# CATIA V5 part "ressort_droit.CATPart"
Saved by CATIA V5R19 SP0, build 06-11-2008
Part number: ressort_droit
Bounding box of the stored display mesh (mm): x 0 to 15, y -117.604 to -3.604, z -8.645 to 31.355
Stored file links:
  H:\EU_thinkMotion\IAO_2010\iao\IAO_MMS_Groupe3\PB\jpeguet\jpeguet_IAO\jpeguet_IAO\ressort_droit.CATPart
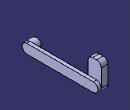
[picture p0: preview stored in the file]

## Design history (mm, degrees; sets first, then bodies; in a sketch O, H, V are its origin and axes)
Parameters
  tige = 100 mm
Body1 (main body)
  Sketch1 on yz-plane, origin (0, 0, 0), H (0, 1, 0), V (0, 0, 1)
    line L1 (-23.6044, 31.3549) -> (-3.6044, 31.3549)
    line L2 (-3.6044, 31.3549) -> (-3.6044, -8.6451)
    line L3 (-3.6044, -8.6451) -> (-23.6044, -8.6451)
    line L4 (-23.6044, -8.6451) -> (-23.6044, 31.3549)
    length L1 = 20
    length L2 = 40
    horizontal: L1 H, L3 H
    vertical: L2 V, L4 V
  Pad1: profile Sketch1, direction (1, 0, 0), length 10
  Sketch2 on start face of Pad1, origin (0, 0, 0), H (0, -1, 0), V (0, 0, 1)
    arc A1 centre (13.6044, 21.3549) radius 7 from (14.6044, 14.4267) to (12.6044, 14.4267) ccw
    point P1 (13.6044, 21.3549)
    point P2 (12.6044, 12.5144)
    line L1 (14.6044, 14.4267) -> (14.6044, 17.3549)
    line L2 (14.6044, 17.3549) -> (12.6044, 17.3549)
    line L3 (12.6044, 17.3549) -> (12.6044, 14.4267)
    point P3 (14.6044, 12.5144)
    reference projected line E1 (23.6044, 31.3549) -> (23.6044, -28.6451) from edge [start face of Pad1 | face of Pad1 from Sketch1.L4]
    reference projected line E2 (3.6044, 31.3549) -> (23.6044, 31.3549) from edge [start face of Pad1 | face of Pad1 from Sketch1.L1]
    reference projected line E3 (23.6044, 31.3549) -> (23.6044, -28.6451) from edge [start face of Pad1 | face of Pad1 from Sketch1.L4]
    reference projected line E4 (3.6044, 31.3549) -> (23.6044, 31.3549) from edge [start face of Pad1 | face of Pad1 from Sketch1.L1]
    distance P1 E1 = 10
    distance E2 P1 = 10
    distance L1 E3 = 9
    radius A1 = 7
    distance L2 E4 = 14
    horizontal: L2 H
    vertical: L1 V, L3 V
  Pocket1: profile Sketch2, direction (1, 0, 0), length 3
  Sketch3 on end face of Pad1, origin (10, 0, 0), H (0, 1, 0), V (0, 0, 1)
    construction line L1 (-10.6044, -1.6451) -> (-110.6044, -1.6451)
    point P1 (-10.6044, -1.6451)
    line L2 (-10.6044, -8.6451) -> (-110.6044, -8.6451)
    line L3 (-110.6044, 5.3549) -> (-10.6044, 5.3549)
    arc A1 centre (-110.6044, -1.6451) radius 7 from (-110.6044, -8.6451) to (-110.6044, 5.3549) cw
    arc A2 centre (-10.6044, -1.6451) radius 7 from (-10.6044, 5.3549) to (-10.6044, -8.6451) cw
    reference projected line E1 (-23.6044, -8.6451) -> (-3.6044, -8.6451) from edge [face of Pad1 from Sketch1.L3 | end face of Pad1]
    reference projected line E2 (-3.6044, -8.6451) -> (-3.6044, 31.3549) from edge [face of Pad1 from Sketch1.L2 | end face of Pad1]
    distance L1 L2 = 7
    distance L1 E1 = 7
    distance P1 E2 = 7
    length L3 = 100 {= tige}
    horizontal: L1 H
    tangency: A1 L2, A2 L2, A1 L3, A2 L3
  Pad2: profile Sketch3, direction (1, 0, 0), length 5
  Fillet1: radius 7, on edge [face of Pad1 from Sketch1.L2 | face of Pad2]
  Fillet2: radius 7, on edge [face of Pad1 from Sketch1.L1 | face of Pad1 from Sketch1.L2]; edge [face of Pad1 from Sketch1.L4 | face of Pad1 from Sketch1.L1]
  Sketch4 on start face of Pad2, origin (10, 0, 0), H (0, -1, 0), V (0, 0, 1)
    circle A1 centre (110.6044, -1.6451) radius 7
    point P1 (110.6044, -1.6451)
    reference projected arc E1 centre (110.6044, -1.6451) radius 7 from (110.6044, -8.6451) to (110.6044, 5.3549) ccw from edge [start face of Pad2 | face of Pad2 from Sketch3.A1]
    radius A1 = 7
    concentricity: P1 E1
  Pad3: profile Sketch4, direction (-1, 0, 0), length 10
